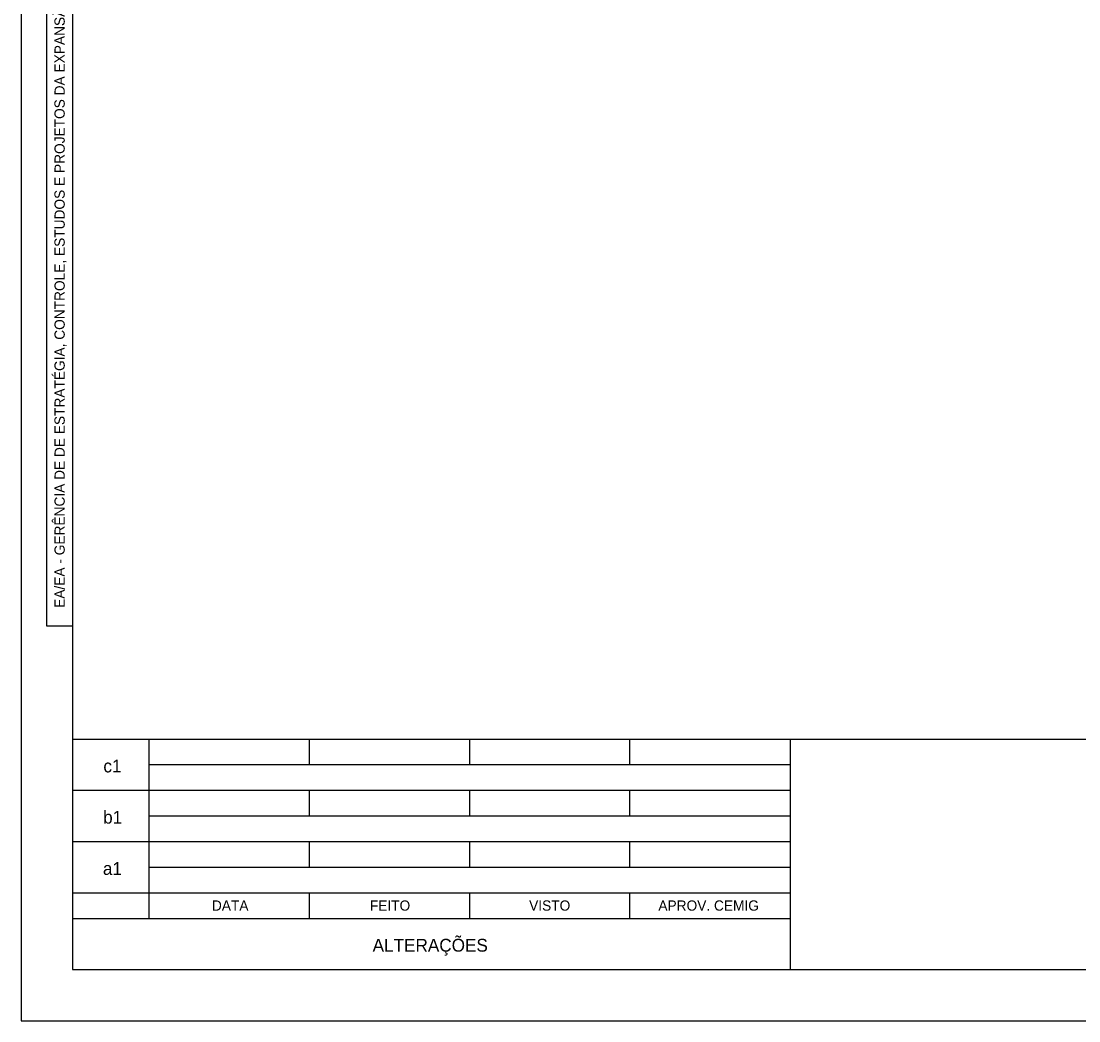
# Model space of a CAD drawing. Extents: x 563 to 1404, y 358 to 952.
# Drawn here: x 562.6 to 768.9, y 358 to 553.1 of the extents above; entities that cross this region are included whole.
import ezdxf

# ---------------------------------------------------------------- set-up
doc = ezdxf.new("R2010")
doc.units = 0
doc.layers.add('New Level (0)', color=7, linetype='Continuous')

msp = doc.modelspace()

# ---------------------------------------------------------------- linework, layer by layer
at = {"layer": 'New Level (0)'}
for p, q in [((562.58, 951.96), (562.58, 357.96)), ((562.58, 951.96), (562.58, 357.96)), ((572.58, 941.96), (572.58, 367.96)), ((572.58, 941.96), (572.58, 367.96)), ((567.58, 434.97), (567.58, 638.29)), ((572.58, 434.97), (567.58, 434.97)), ((572.58, 412.96), (1393.58, 412.96)), ((587.58, 377.96), (587.58, 412.96)), ((618.83, 407.96), (618.83, 412.96)), ((650.08, 407.96), (650.08, 412.96)), ((681.33, 407.96), (681.33, 412.96)), ((712.58, 412.96), (712.58, 367.96)), ((587.58, 407.96), (712.58, 407.96)), ((572.58, 402.96), (712.58, 402.96)), ((618.83, 397.96), (618.83, 402.96)), ((650.08, 397.96), (650.08, 402.96)), ((681.33, 397.96), (681.33, 402.96)), ((587.58, 397.96), (712.58, 397.96)), ((572.58, 392.96), (712.58, 392.96)), ((618.83, 387.96), (618.83, 392.96)), ((650.08, 387.96), (650.08, 392.96)), ((681.33, 387.96), (681.33, 392.96)), ((587.58, 387.96), (712.58, 387.96)), ((572.58, 382.96), (712.58, 382.96)), ((618.83, 377.96), (618.83, 382.96)), ((650.08, 377.96), (650.08, 382.96)), ((681.33, 377.96), (681.33, 382.96)), ((572.58, 377.96), (712.58, 377.96)), ((572.58, 367.96), (1393.58, 367.96)), ((572.58, 367.96), (1393.58, 367.96)), ((562.58, 357.96), (1403.58, 357.96)), ((562.58, 357.96), (1403.58, 357.96))]:
    msp.add_line(p, q, dxfattribs=at)

# ---------------------------------------------------------------- texts
msp.add_text('EA/EA - GERÊNCIA DE DE ESTRATÉGIA, CONTROLE, ESTUDOS E PROJETOS DA EXPANSÃO E MANUTENÇÃO DA  ALTA TENSÃO DA DISTRIBUIÇÃO', height=2, rotation=90, dxfattribs=at).set_placement((571.08, 438.56))
for s, height, p in [('c1', 2.5, (578.62, 406.44)), ('b1', 2.5, (578.57, 396.44)), ('a1', 2.5, (578.52, 386.44)), ('DATA', 2, (599.79, 379.46)), ('FEITO', 2, (630.6, 379.46)), ('VISTO', 2, (661.67, 379.46)), ('APROV. CEMIG', 2, (686.88, 379.46)), ('ALTERAÇÕES', 2.5, (631.14, 371.46))]:
    msp.add_text(s, height=height, dxfattribs=at).set_placement(p)

doc.saveas('drawing.dxf')
